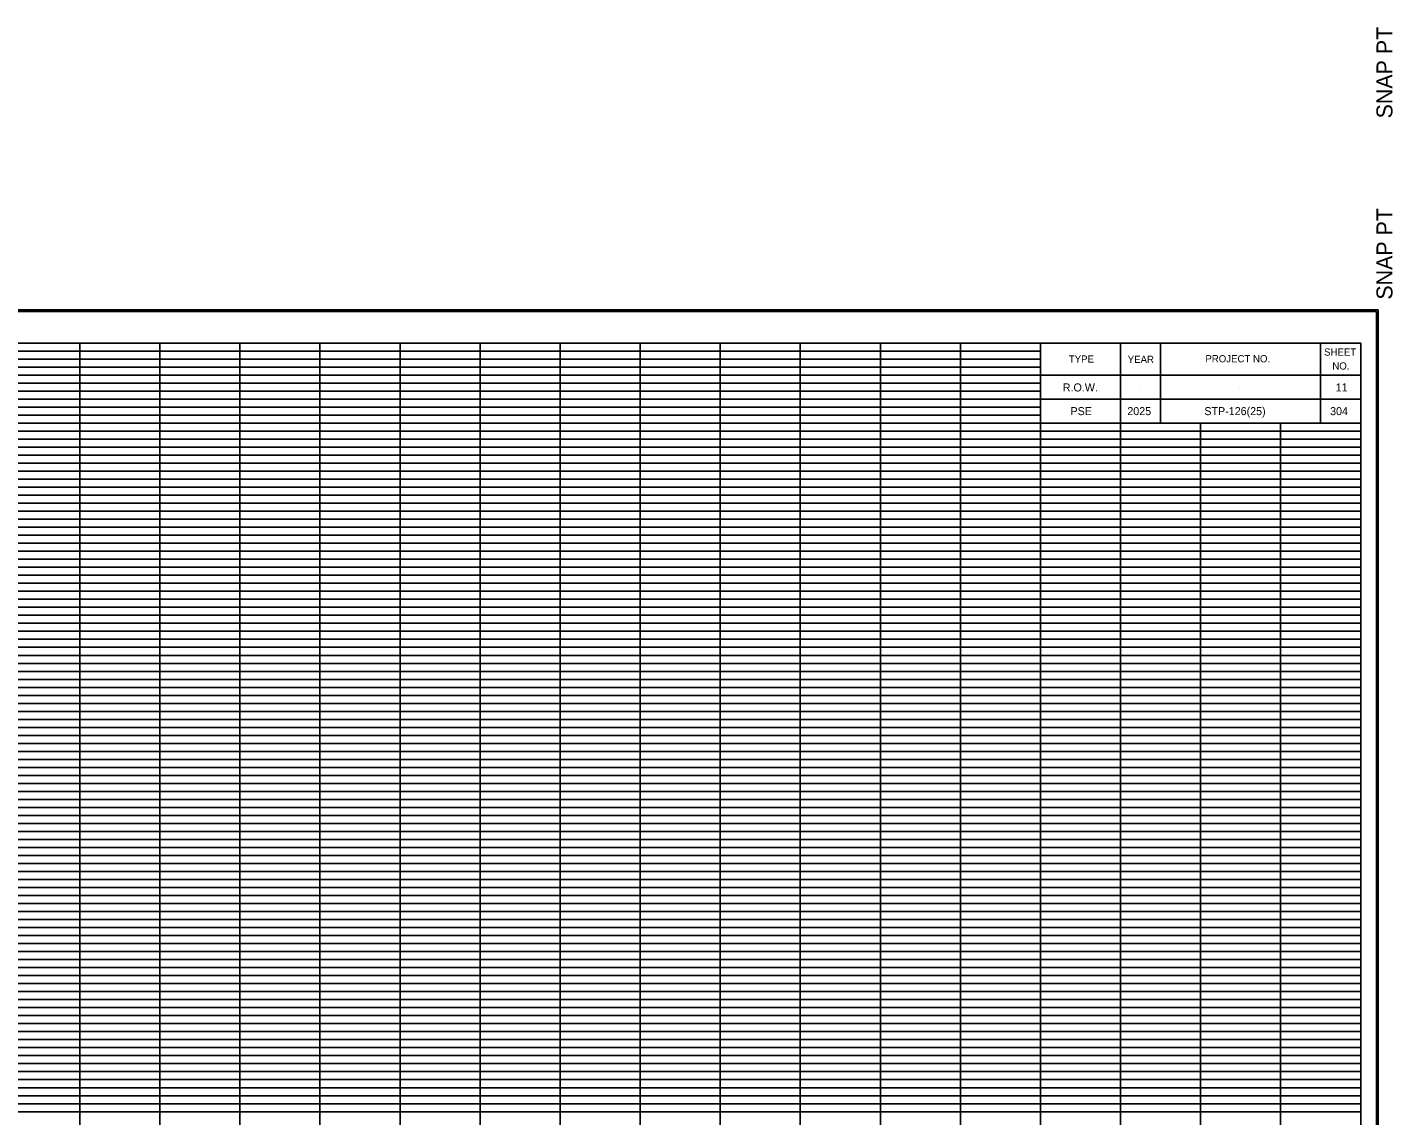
# Model space of a CAD drawing. Extents: x 980 to 2064, y 978 to 2267.
# Drawn here: x 1893.4 to 2064, y 1113.5 to 1249.4 of the extents above; entities that cross this region are included whole.
import ezdxf

# ---------------------------------------------------------------- set-up
doc = ezdxf.new("R2010")
doc.units = 0
for name, color, linetype in [('Default', 7, 'Continuous'), ('DESIGN - SCRATCH - User 1', 7, 'Continuous'), ('DESIGN - SHEET - Corner Text', 7, 'Continuous'), ('DESIGN - SHEET - Light Grid', 7, 'Continuous'), ('DESIGN - SHEET - Linework', 7, 'Continuous'), ('DESIGN - SHEET - Plot Shape', 7, 'Continuous')]:
    doc.layers.add(name, color=color, linetype=linetype)

# ---------------------------------------------------------------- blocks, each defined once
blk = doc.blocks.new('XSTSHT')
at = {"layer": 'DESIGN - SCRATCH - User 1'}
for p, q in [((28.5, 20.45), (28.5, 20.45)), ((29.24, 20.45), (29.24, 20.45)), ((30.49, 20.45), (30.49, 20.45)), ((31.74, 20.45), (31.74, 20.45)), ((28.5, 20.15), (28.5, 20.15)), ((29.24, 20.15), (29.24, 20.15)), ((30.49, 20.15), (30.49, 20.15)), ((31.74, 20.15), (31.74, 20.15))]:
    blk.add_line(p, q, dxfattribs=at)
at = {"layer": 'DESIGN - SHEET - Light Grid'}
for p, q in [((8, 20.9), (16, 20.9)), ((16, 20.9), (24, 20.9)), ((24, 20.9), (28, 20.9)), ((8, 20.8), (16, 20.8)), ((8, 20.7), (16, 20.7)), ((16, 20.8), (24, 20.8)), ((16, 20.7), (24, 20.7)), ((24, 20.8), (28, 20.8)), ((24, 20.7), (28, 20.7)), ((8, 20.6), (16, 20.6)), ((8, 20.5), (16, 20.5)), ((16, 20.6), (24, 20.6)), ((16, 20.5), (24, 20.5)), ((24, 20.6), (28, 20.6)), ((24, 20.5), (28, 20.5)), ((8, 20.4), (16, 20.4)), ((8, 20.3), (16, 20.3)), ((16, 20.4), (24, 20.4)), ((16, 20.3), (24, 20.3)), ((24, 20.4), (28, 20.4)), ((24, 20.3), (28, 20.3)), ((8, 20.2), (16, 20.2)), ((16, 20.2), (24, 20.2)), ((24, 20.2), (28, 20.2)), ((8, 20.1), (16, 20.1)), ((16, 20.1), (24, 20.1)), ((24, 20.1), (28, 20.1)), ((8, 19.9), (16, 19.9)), ((8, 19.8), (16, 19.8)), ((16, 19.9), (24, 19.9)), ((16, 19.8), (24, 19.8)), ((24, 19.9), (32, 19.9)), ((24, 19.8), (32, 19.8)), ((8, 19.7), (16, 19.7)), ((16, 19.7), (24, 19.7)), ((24, 19.7), (32, 19.7)), ((8, 19.6), (16, 19.6)), ((8, 19.5), (16, 19.5)), ((16, 19.6), (24, 19.6)), ((16, 19.5), (24, 19.5)), ((24, 19.6), (32, 19.6)), ((24, 19.5), (32, 19.5)), ((8, 19.4), (16, 19.4)), ((8, 19.3), (16, 19.3)), ((16, 19.4), (24, 19.4)), ((16, 19.3), (24, 19.3)), ((24, 19.4), (32, 19.4)), ((24, 19.3), (32, 19.3)), ((8, 19.2), (16, 19.2)), ((16, 19.2), (24, 19.2)), ((24, 19.2), (32, 19.2)), ((8, 19.1), (16, 19.1)), ((16, 19.1), (24, 19.1)), ((24, 19.1), (32, 19.1)), ((8, 18.9), (16, 18.9)), ((8, 18.8), (16, 18.8)), ((16, 18.9), (24, 18.9)), ((16, 18.8), (24, 18.8)), ((24, 18.9), (32, 18.9)), ((24, 18.8), (32, 18.8)), ((8, 18.7), (16, 18.7)), ((8, 18.6), (16, 18.6)), ((16, 18.7), (24, 18.7)), ((16, 18.6), (24, 18.6)), ((24, 18.7), (32, 18.7)), ((24, 18.6), (32, 18.6)), ((8, 18.5), (16, 18.5)), ((16, 18.5), (24, 18.5)), ((24, 18.5), (32, 18.5)), ((8, 18.4), (16, 18.4)), ((8, 18.3), (16, 18.3)), ((16, 18.4), (24, 18.4)), ((16, 18.3), (24, 18.3)), ((24, 18.4), (32, 18.4)), ((24, 18.3), (32, 18.3)), ((8, 18.2), (16, 18.2)), ((8, 18.1), (16, 18.1)), ((16, 18.2), (24, 18.2)), ((16, 18.1), (24, 18.1)), ((24, 18.2), (32, 18.2)), ((24, 18.1), (32, 18.1)), ((8, 17.9), (16, 17.9)), ((8, 17.8), (16, 17.8)), ((16, 17.9), (24, 17.9)), ((16, 17.8), (24, 17.8)), ((24, 17.9), (32, 17.9)), ((24, 17.8), (32, 17.8)), ((8, 17.7), (16, 17.7)), ((8, 17.6), (16, 17.6)), ((16, 17.7), (24, 17.7)), ((16, 17.6), (24, 17.6)), ((24, 17.7), (32, 17.7)), ((24, 17.6), (32, 17.6)), ((8, 17.5), (16, 17.5)), ((8, 17.4), (16, 17.4)), ((16, 17.5), (24, 17.5)), ((16, 17.4), (24, 17.4)), ((24, 17.5), (32, 17.5)), ((24, 17.4), (32, 17.4)), ((8, 17.3), (16, 17.3)), ((16, 17.3), (24, 17.3)), ((24, 17.3), (32, 17.3)), ((8, 17.2), (16, 17.2)), ((8, 17.1), (16, 17.1)), ((16, 17.2), (24, 17.2)), ((16, 17.1), (24, 17.1)), ((24, 17.2), (32, 17.2)), ((24, 17.1), (32, 17.1)), ((8, 16.9), (16, 16.9)), ((16, 16.9), (24, 16.9)), ((24, 16.9), (32, 16.9)), ((8, 16.8), (16, 16.8)), ((16, 16.8), (24, 16.8)), ((24, 16.8), (32, 16.8)), ((8, 16.7), (16, 16.7)), ((8, 16.6), (16, 16.6)), ((16, 16.7), (24, 16.7)), ((16, 16.6), (24, 16.6)), ((24, 16.7), (32, 16.7)), ((24, 16.6), (32, 16.6)), ((8, 16.5), (16, 16.5)), ((8, 16.4), (16, 16.4)), ((16, 16.5), (24, 16.5)), ((16, 16.4), (24, 16.4)), ((24, 16.5), (32, 16.5)), ((24, 16.4), (32, 16.4)), ((8, 16.3), (16, 16.3)), ((16, 16.3), (24, 16.3)), ((24, 16.3), (32, 16.3)), ((8, 16.2), (16, 16.2)), ((8, 16.1), (16, 16.1)), ((16, 16.2), (24, 16.2)), ((16, 16.1), (24, 16.1)), ((24, 16.2), (32, 16.2)), ((24, 16.1), (32, 16.1)), ((8, 15.9), (16, 15.9)), ((16, 15.9), (24, 15.9)), ((24, 15.9), (32, 15.9)), ((8, 15.8), (16, 15.8)), ((8, 15.7), (16, 15.7)), ((16, 15.8), (24, 15.8)), ((16, 15.7), (24, 15.7)), ((24, 15.8), (32, 15.8)), ((24, 15.7), (32, 15.7)), ((8, 15.6), (16, 15.6)), ((16, 15.6), (24, 15.6)), ((24, 15.6), (32, 15.6)), ((8, 15.5), (16, 15.5)), ((8, 15.4), (16, 15.4)), ((16, 15.5), (24, 15.5)), ((16, 15.4), (24, 15.4)), ((24, 15.5), (32, 15.5)), ((24, 15.4), (32, 15.4)), ((8, 15.3), (16, 15.3)), ((8, 15.2), (16, 15.2)), ((16, 15.3), (24, 15.3)), ((16, 15.2), (24, 15.2)), ((24, 15.3), (32, 15.3)), ((24, 15.2), (32, 15.2)), ((8, 15.1), (16, 15.1)), ((16, 15.1), (24, 15.1)), ((24, 15.1), (32, 15.1)), ((8, 14.9), (16, 14.9)), ((16, 14.9), (24, 14.9)), ((24, 14.9), (32, 14.9)), ((8, 14.8), (16, 14.8)), ((8, 14.7), (16, 14.7)), ((16, 14.8), (24, 14.8)), ((16, 14.7), (24, 14.7)), ((24, 14.8), (32, 14.8)), ((24, 14.7), (32, 14.7)), ((8, 14.6), (16, 14.6)), ((8, 14.5), (16, 14.5)), ((16, 14.6), (24, 14.6)), ((16, 14.5), (24, 14.5)), ((24, 14.6), (32, 14.6)), ((24, 14.5), (32, 14.5)), ((8, 14.4), (16, 14.4)), ((16, 14.4), (24, 14.4)), ((24, 14.4), (32, 14.4)), ((8, 14.3), (16, 14.3)), ((8, 14.2), (16, 14.2)), ((16, 14.3), (24, 14.3)), ((16, 14.2), (24, 14.2)), ((24, 14.3), (32, 14.3)), ((24, 14.2), (32, 14.2)), ((8, 14.1), (16, 14.1)), ((16, 14.1), (24, 14.1)), ((24, 14.1), (32, 14.1)), ((8, 13.9), (16, 13.9)), ((16, 13.9), (24, 13.9)), ((24, 13.9), (32, 13.9)), ((8, 13.8), (16, 13.8)), ((8, 13.7), (16, 13.7)), ((16, 13.8), (24, 13.8)), ((16, 13.7), (24, 13.7)), ((24, 13.8), (32, 13.8)), ((24, 13.7), (32, 13.7)), ((8, 13.6), (16, 13.6)), ((8, 13.5), (16, 13.5)), ((16, 13.6), (24, 13.6)), ((16, 13.5), (24, 13.5)), ((24, 13.6), (32, 13.6)), ((24, 13.5), (32, 13.5)), ((8, 13.4), (16, 13.4)), ((16, 13.4), (24, 13.4)), ((24, 13.4), (32, 13.4)), ((8, 13.3), (16, 13.3)), ((8, 13.2), (16, 13.2)), ((16, 13.3), (24, 13.3)), ((16, 13.2), (24, 13.2)), ((24, 13.3), (32, 13.3)), ((24, 13.2), (32, 13.2)), ((8, 13.1), (16, 13.1)), ((16, 13.1), (24, 13.1)), ((24, 13.1), (32, 13.1)), ((8, 12.9), (16, 12.9)), ((8, 12.8), (16, 12.8)), ((16, 12.9), (24, 12.9)), ((16, 12.8), (24, 12.8)), ((24, 12.9), (32, 12.9)), ((24, 12.8), (32, 12.8)), ((8, 12.7), (16, 12.7)), ((16, 12.7), (24, 12.7)), ((24, 12.7), (32, 12.7)), ((8, 12.6), (16, 12.6)), ((8, 12.5), (16, 12.5)), ((16, 12.6), (24, 12.6)), ((16, 12.5), (24, 12.5)), ((24, 12.6), (32, 12.6)), ((24, 12.5), (32, 12.5)), ((8, 12.4), (16, 12.4)), ((8, 12.3), (16, 12.3)), ((16, 12.4), (24, 12.4)), ((16, 12.3), (24, 12.3)), ((24, 12.4), (32, 12.4)), ((24, 12.3), (32, 12.3)), ((8, 12.2), (16, 12.2)), ((16, 12.2), (24, 12.2)), ((24, 12.2), (32, 12.2)), ((8, 12.1), (16, 12.1)), ((16, 12.1), (24, 12.1)), ((24, 12.1), (32, 12.1)), ((8, 11.9), (16, 11.9)), ((8, 11.8), (16, 11.8)), ((16, 11.9), (24, 11.9)), ((16, 11.8), (24, 11.8)), ((24, 11.9), (32, 11.9)), ((24, 11.8), (32, 11.8)), ((8, 11.7), (16, 11.7)), ((8, 11.6), (16, 11.6)), ((16, 11.7), (24, 11.7)), ((16, 11.6), (24, 11.6)), ((24, 11.7), (32, 11.7)), ((24, 11.6), (32, 11.6)), ((8, 11.5), (16, 11.5)), ((16, 11.5), (24, 11.5)), ((24, 11.5), (32, 11.5)), ((8, 11.4), (16, 11.4)), ((16, 11.4), (24, 11.4)), ((24, 11.4), (32, 11.4))]:
    blk.add_line(p, q, dxfattribs=at)
at = {"layer": 'DESIGN - SHEET - Linework'}
for p, q in [((-1.823, 21.414), (32.217, 21.414)), ((32.217, 21.414), (32.217, -0.414)), ((16, 0), (16, 21)), ((17, 0), (17, 21)), ((18, 0), (18, 21)), ((19, 0), (19, 21)), ((20, 0), (20, 21)), ((21, 0), (21, 21)), ((22, 0), (22, 21)), ((23, 0), (23, 21)), ((24, 0), (24, 21)), ((25, 0), (25, 21)), ((26, 0), (26, 21)), ((27, 0), (27, 21)), ((0, 20), (28, 20)), ((28, 0), (28, 20)), ((29, 0), (29, 20)), ((30, 0), (30, 20)), ((31, 0), (31, 20)), ((0, 19), (32, 19)), ((0, 18), (32, 18)), ((0, 17), (32, 17)), ((0, 16), (32, 16)), ((0, 15), (32, 15)), ((0, 14), (32, 14)), ((0, 13), (32, 13)), ((0, 12), (32, 12))]:
    blk.add_line(p, q, dxfattribs=at)
for points in [[(0, 21), (0, 0), (32, 0), (32, 21), (0, 21)], [(28, 21), (28, 20), (32, 20), (32, 21), (31.5, 21), (31.5, 20), (29.5, 20), (29.5, 21), (29, 21), (29, 20), (32, 20), (28, 20), (28, 20.3), (32, 20.3), (32, 20.6), (28, 20.6)]]:
    blk.add_lwpolyline(points, dxfattribs=at)
at = {"layer": 'DESIGN - SHEET - Plot Shape'}
for points in [[(-1.803, 21.394), (32.197, 21.394), (32.197, -0.394), (-1.803, -0.394)], [(-0.85, 21), (32, 21), (32, -0.25), (-0.85, -0.25)]]:
    blk.add_lwpolyline(points, close=True, dxfattribs=at)
at = {"layer": 'DESIGN - SHEET - Corner Text'}
for s, p in [('  SNAP PT', (32.397, 21.394)), ('SNAP PT  ', (32.397, -2.194))]:
    blk.add_text(s, height=0.2, rotation=90, dxfattribs=at).set_placement(p)
for s, p in [('TYPE', (28.354, 20.756)), ('YEAR', (29.09, 20.752)), ('PROJECT NO.', (30.06, 20.76)), ('SHEET', (31.543, 20.843)), ('NO.', (31.646, 20.669))]:
    blk.add_text(s, height=0.09, dxfattribs=at).set_placement(p)

msp = doc.modelspace()

# ---------------------------------------------------------------- block references
at = {"layer": 'Default', "xscale": 10, "yscale": 10}
for p in [(1740, 1260), (1740, 1000)]:
    msp.add_blockref('XSTSHT', p, dxfattribs=at)

# ---------------------------------------------------------------- texts
at = {"layer": 'DESIGN - SHEET - Corner Text'}
for s, p in [('R.O.W.', (2022.79, 1203.96)), ('11', (2056.87, 1203.96)), ('PSE', (2023.75, 1201)), ('2025', (2030.85, 1201)), ('STP-126(25)', (2040.47, 1201)), ('304', (2056.18, 1201))]:
    msp.add_text(s, height=1, dxfattribs=at).set_placement(p)

doc.saveas('drawing.dxf')
